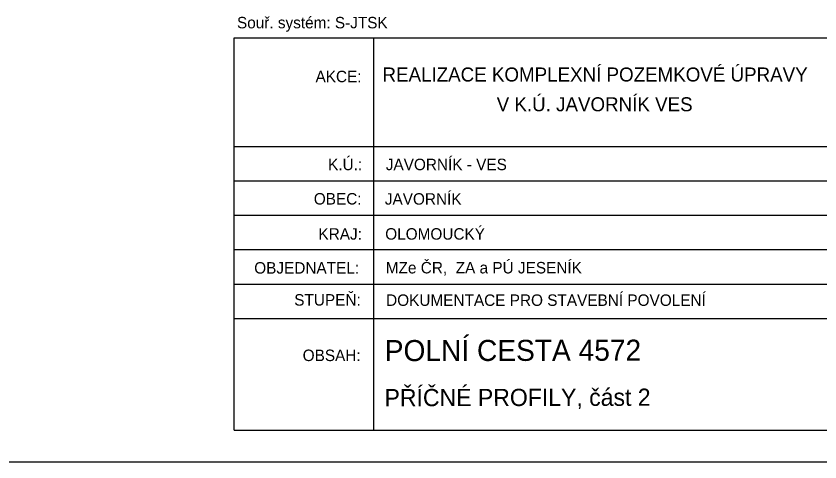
# Model space of a CAD drawing. Extents: x -552501 to -552394, y -1029983 to -1029892.
# Drawn here: x -552414.17 to -552401.56, y -1029952.75 to -1029945.76 of the extents above; entities that cross this region are included whole.
import ezdxf

# ---------------------------------------------------------------- set-up
doc = ezdxf.new("R2010")
doc.units = 0
doc.layers.add('rámeček', color=7, linetype='Continuous')

msp = doc.modelspace()

# ---------------------------------------------------------------- linework, layer by layer
at = {"layer": 'rámeček'}
for p, q in [((-552410.755, -1029946.095), (-552395.255, -1029946.095)), ((-552410.755, -1029952.25), (-552410.755, -1029946.095)), ((-552408.562, -1029952.25), (-552408.562, -1029946.095)), ((-552410.755, -1029947.802), (-552395.255, -1029947.802)), ((-552410.755, -1029948.341), (-552395.255, -1029948.341)), ((-552410.755, -1029948.881), (-552395.255, -1029948.881)), ((-552410.755, -1029949.42), (-552395.255, -1029949.42)), ((-552410.755, -1029949.959), (-552395.255, -1029949.959)), ((-552410.755, -1029950.498), (-552396.745, -1029950.498)), ((-552410.755, -1029952.25), (-552395.255, -1029952.25)), ((-552499.755, -1029952.75), (-552394.755, -1029952.75)), ((-552499.755, -1029952.75), (-552394.755, -1029952.75)), ((-552499.755, -1029952.75), (-552394.755, -1029952.75))]:
    msp.add_line(p, q, dxfattribs=at)

# ---------------------------------------------------------------- texts
for s, height, rotation, p in [('Souř. systém: S-JTSK', 0.17971, 0, (-552410.708, -1029945.948)), ('REALIZACE KOMPLEXNÍ POZEMKOVÉ ÚPRAVY', 0.22, 0, (-552408.426, -1029946.782)), ('AKCE:', 0.1797, 0, (-552409.476, -1029946.793)), (' V K.Ú. JAVORNÍK VES', 0.22, 0, (-552406.716, -1029947.249)), ('K.Ú.:', 0.18, 0, (-552409.279, -1029948.173)), ('JAVORNÍK - VES', 0.18, 0, (-552408.374, -1029948.173)), ('OBEC:', 0.18, 0, (-552409.503, -1029948.712)), ('JAVORNÍK', 0.18, 0, (-552408.389, -1029948.714)), ('KRAJ:', 0.18, 0, (-552409.43, -1029949.263)), ('OLOMOUCKÝ', 0.18, 0, (-552408.383, -1029949.263)), ('MZe ČR,  ZA a PÚ JESENÍK', 0.18, 0, (-552408.374, -1029949.793)), ('OBJEDNATEL:', 0.18, 0, (-552410.438, -1029949.796)), ('STUPEŇ:', 0.18, 0, (-552409.81, -1029950.298)), ('DOKUMENTACE PRO STAVEBNÍ POVOLENÍ', 0.18, 0, (-552408.369, -1029950.302)), ('POLNÍ CESTA 4572', 0.33, 0.1038, (-552408.39, -1029951.169)), ('OBSAH:', 0.18, 0, (-552409.678, -1029951.168)), ('PŘÍČNÉ PROFILY, část 2', 0.27, 0.1038, (-552408.393, -1029951.877))]:
    msp.add_text(s, height=height, rotation=rotation, dxfattribs=at).set_placement(p)

doc.saveas('drawing.dxf')
